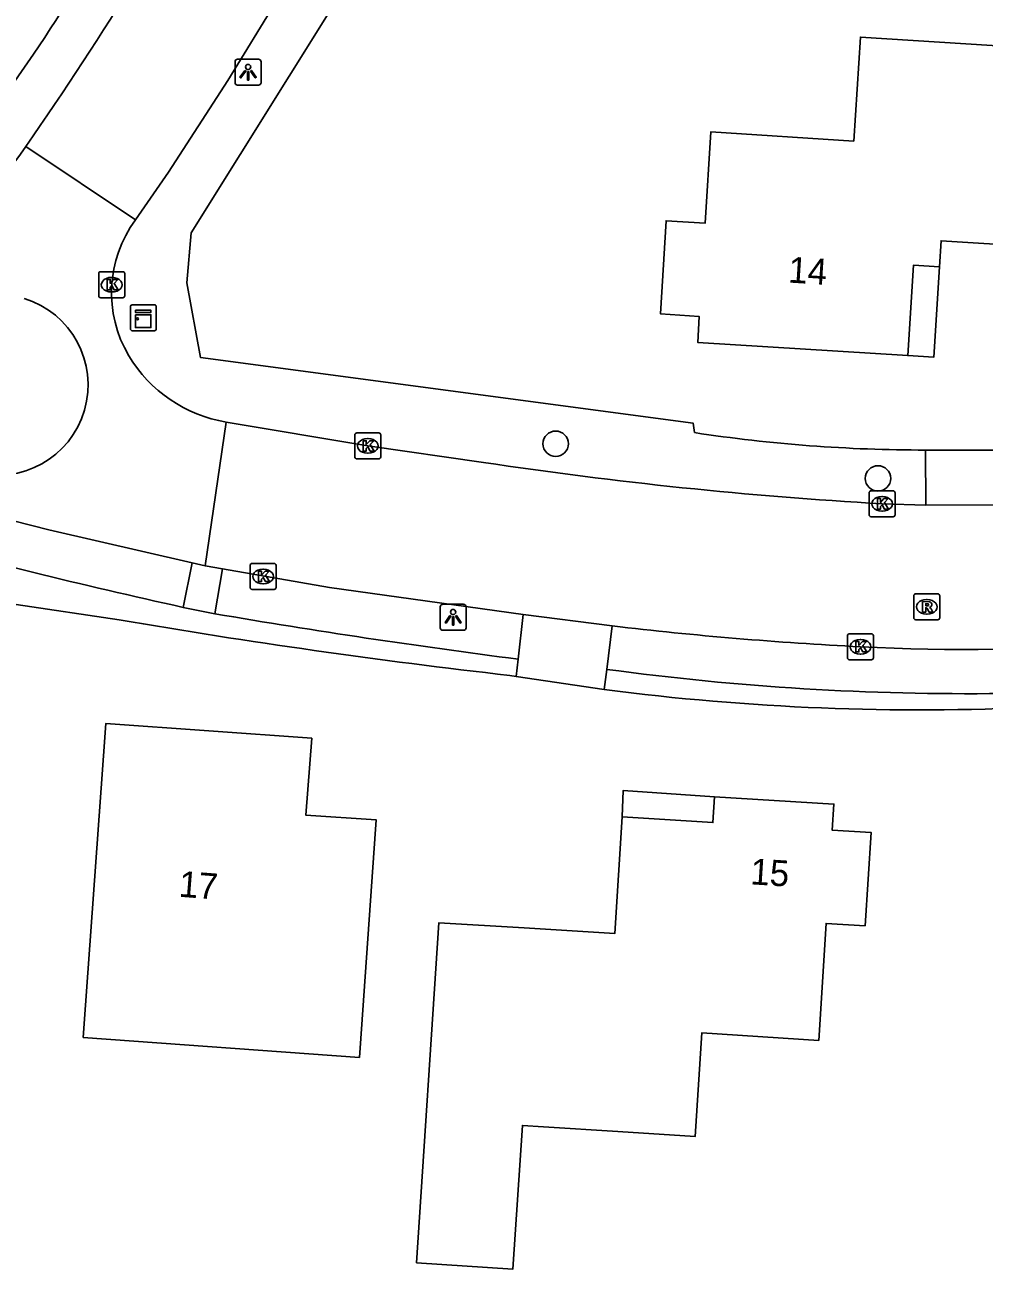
# Model space of a CAD drawing. Extents: x 162675 to 163482, y 379761 to 381227.
# Drawn here: x 163128.52 to 163165.45, y 380867.2 to 380915.09 of the extents above; entities that cross this region are included whole.
import ezdxf

# ---------------------------------------------------------------- set-up
doc = ezdxf.new("R2010")
doc.units = 0
for name, color, linetype in [('IMGEO_Berm_groen', 7, 'Continuous'), ('IMGEO_Boom', 7, 'Continuous'), ('IMGEO_Groenvoorziening', 7, 'Continuous'), ('IMGEO_Haag', 7, 'Continuous'), ('IMGEO_Hek', 7, 'Continuous'), ('IMGEO_Kast', 7, 'Continuous'), ('IMGEO_Kolk', 7, 'Continuous'), ('IMGEO_Lichtpunt', 7, 'Continuous'), ('IMGEO_Pand', 7, 'Continuous'), ('IMGEO_Pand_nummerreeks', 7, 'Continuous'), ('IMGEO_Pand_overbouw', 7, 'Continuous'), ('IMGEO_Parkeervlak_halfverhard', 7, 'Continuous'), ('IMGEO_Rijbaan_lokaal_gesloten', 7, 'Continuous'), ('IMGEO_Rijbaan_lokaal_open', 7, 'Continuous'), ('IMGEO_Rioolput', 7, 'Continuous'), ('IMGEO_Voetpad_open', 7, 'Continuous')]:
    doc.layers.add(name, color=color, linetype=linetype)

msp = doc.modelspace()

# ---------------------------------------------------------------- linework, layer by layer
at = {"layer": 'IMGEO_Berm_groen'}
msp.add_lwpolyline([(163150.959, 380936.325), (163144.291, 380922.073), (163134.917, 380907.085), (163134.757, 380905.164), (163135.284, 380902.281), (163154.247, 380899.765), (163154.294, 380899.394)], dxfattribs=at)
msp.add_arc((163163.182, 380958.103), 59.378, 261.39114, 270.01327, dxfattribs=at)
at = {"layer": 'IMGEO_Boom'}
for centre in [(163148.955, 380898.967), (163161.365, 380897.632)]:
    msp.add_circle(centre, 0.489, dxfattribs=at)
at = {"layer": 'IMGEO_Groenvoorziening'}
for points in [[(163128.179, 380892.783), (163132.144, 380892.19)], [(163147.191, 380890.047), (163147.437, 380890.008)]]:
    msp.add_lwpolyline(points, dxfattribs=at)
msp.add_arc((163177.842, 381159.158), 270.851, 260.28663, 263.50221, dxfattribs=at)
at = {"layer": 'IMGEO_Haag'}
msp.add_arc((163162.97, 380982.847), 94.126, 262.58307, 283.03541, dxfattribs=at)
at = {"layer": 'IMGEO_Hek'}
for points in [[(163134.917, 380907.085), (163144.291, 380922.073), (163150.959, 380936.325)], [(163154.247, 380899.765), (163135.284, 380902.281), (163134.757, 380905.164), (163134.917, 380907.085)]]:
    msp.add_lwpolyline(points, dxfattribs=at)
at = {"layer": 'IMGEO_Kast'}
for p, q in [((163132.654, 380904.315), (163133.495, 380904.315)), ((163133.495, 380904.315), (163132.654, 380904.315)), ((163132.579, 380903.39), (163132.579, 380904.231)), ((163132.579, 380904.231), (163132.579, 380903.39)), ((163133.579, 380904.24), (163133.579, 380903.399)), ((163133.579, 380903.399), (163133.579, 380904.24)), ((163133.504, 380903.315), (163132.663, 380903.315)), ((163132.663, 380903.315), (163133.504, 380903.315))]:
    msp.add_line(p, q, dxfattribs=at)
for points in [[(163132.774, 380904.105), (163133.374, 380904.105), (163133.374, 380904.02), (163132.774, 380904.02), (163132.774, 380904.105)], [(163132.774, 380903.93), (163133.374, 380903.93), (163133.374, 380903.441), (163132.774, 380903.441), (163132.774, 380903.93)]]:
    msp.add_lwpolyline(points, dxfattribs=at)
msp.add_circle((163132.858, 380903.779), 0.0377, dxfattribs=at)
for centre, start, end in [((163132.657, 380904.237), 92.4484, 184.2845), ((163132.657, 380904.237), 92.4484, 184.2845), ((163133.501, 380904.237), 2.4484, 94.2845), ((163133.501, 380904.237), 2.4484, 94.2845), ((163132.657, 380903.393), 182.4484, 274.2845), ((163132.657, 380903.393), 182.4484, 274.2845), ((163133.501, 380903.393), 272.4484, 4.2845), ((163133.501, 380903.393), 272.4484, 4.2845)]:
    msp.add_arc(centre, 0.0779, start, end, dxfattribs=at)
at = {"layer": 'IMGEO_Kolk'}
for p, q in [((163131.362, 380904.664), (163131.362, 380905.516)), ((163131.437, 380905.59), (163132.289, 380905.59)), ((163131.85, 380905.37), (163131.875, 380905.37)), ((163132.363, 380905.516), (163132.363, 380904.664)), ((163131.873, 380904.81), (163131.848, 380904.81)), ((163132.289, 380904.59), (163131.437, 380904.59)), ((163141.221, 380898.458), (163141.221, 380899.31)), ((163141.296, 380899.384), (163142.148, 380899.384)), ((163141.709, 380899.164), (163141.734, 380899.164)), ((163142.222, 380899.31), (163142.222, 380898.458)), ((163141.732, 380898.604), (163141.707, 380898.604)), ((163142.148, 380898.384), (163141.296, 380898.384)), ((163161.097, 380897.155), (163161.949, 380897.155)), ((163161.022, 380896.229), (163161.022, 380897.081)), ((163161.51, 380896.935), (163161.535, 380896.935)), ((163162.023, 380897.081), (163162.023, 380896.229)), ((163161.533, 380896.375), (163161.508, 380896.375)), ((163161.949, 380896.155), (163161.097, 380896.155)), ((163137.191, 380893.433), (163137.191, 380894.285)), ((163137.266, 380894.359), (163138.118, 380894.359)), ((163138.192, 380894.285), (163138.192, 380893.433)), ((163137.679, 380894.139), (163137.704, 380894.139)), ((163138.118, 380893.359), (163137.266, 380893.359)), ((163137.702, 380893.579), (163137.677, 380893.579)), ((163160.189, 380890.726), (163160.189, 380891.578)), ((163160.264, 380891.652), (163161.116, 380891.652)), ((163160.677, 380891.432), (163160.702, 380891.432)), ((163161.19, 380891.578), (163161.19, 380890.726)), ((163161.116, 380890.652), (163160.264, 380890.652)), ((163160.7, 380890.872), (163160.675, 380890.872))]:
    msp.add_line(p, q, dxfattribs=at)
for points in [[(163131.362, 380904.664), (163131.362, 380905.516)], [(163131.437, 380905.59), (163132.289, 380905.59)], [(163131.683, 380905.29), (163131.806, 380905.29), (163131.806, 380905.139), (163131.936, 380905.29), (163132.1, 380905.29), (163131.954, 380905.139), (163132.107, 380904.89), (163131.955, 380904.89), (163131.87, 380905.054), (163131.806, 380904.987), (163131.806, 380904.89), (163131.683, 380904.89), (163131.683, 380905.29)], [(163132.363, 380905.516), (163132.363, 380904.664)], [(163132.289, 380904.59), (163131.437, 380904.59)], [(163141.221, 380898.458), (163141.221, 380899.31)], [(163141.296, 380899.384), (163142.148, 380899.384)], [(163141.542, 380899.084), (163141.665, 380899.084), (163141.665, 380898.933), (163141.795, 380899.084), (163141.959, 380899.084), (163141.813, 380898.933), (163141.966, 380898.684), (163141.814, 380898.684), (163141.729, 380898.848), (163141.665, 380898.781), (163141.665, 380898.684), (163141.542, 380898.684), (163141.542, 380899.084)], [(163142.222, 380899.31), (163142.222, 380898.458)], [(163142.148, 380898.384), (163141.296, 380898.384)], [(163161.097, 380897.155), (163161.949, 380897.155)], [(163161.022, 380896.229), (163161.022, 380897.081)], [(163161.343, 380896.855), (163161.466, 380896.855), (163161.466, 380896.704), (163161.596, 380896.855), (163161.76, 380896.855), (163161.614, 380896.704), (163161.767, 380896.455), (163161.615, 380896.455), (163161.53, 380896.619), (163161.466, 380896.552), (163161.466, 380896.455), (163161.343, 380896.455), (163161.343, 380896.855)], [(163162.023, 380897.081), (163162.023, 380896.229)], [(163161.949, 380896.155), (163161.097, 380896.155)], [(163137.191, 380893.433), (163137.191, 380894.285)], [(163137.266, 380894.359), (163138.118, 380894.359)], [(163138.192, 380894.285), (163138.192, 380893.433)], [(163137.512, 380894.059), (163137.635, 380894.059), (163137.635, 380893.908), (163137.765, 380894.059), (163137.929, 380894.059), (163137.783, 380893.908), (163137.936, 380893.659), (163137.784, 380893.659), (163137.699, 380893.823), (163137.635, 380893.756), (163137.635, 380893.659), (163137.512, 380893.659), (163137.512, 380894.059)], [(163138.118, 380893.359), (163137.266, 380893.359)], [(163160.189, 380890.726), (163160.189, 380891.578)], [(163160.264, 380891.652), (163161.116, 380891.652)], [(163161.19, 380891.578), (163161.19, 380890.726)], [(163160.51, 380891.352), (163160.633, 380891.352), (163160.633, 380891.201), (163160.763, 380891.352), (163160.927, 380891.352), (163160.781, 380891.201), (163160.934, 380890.952), (163160.782, 380890.952), (163160.697, 380891.116), (163160.633, 380891.049), (163160.633, 380890.952), (163160.51, 380890.952), (163160.51, 380891.352)], [(163161.116, 380890.652), (163160.264, 380890.652)]]:
    msp.add_lwpolyline(points, dxfattribs=at)
for centre, start, end in [((163131.439, 380905.514), 91.552, 178.448), ((163131.439, 380905.514), 91.552, 178.448), ((163132.287, 380905.514), 1.552, 88.448), ((163132.287, 380905.514), 1.552, 88.448), ((163131.439, 380904.666), 181.552, 268.448), ((163131.439, 380904.666), 181.552, 268.448), ((163132.287, 380904.666), 271.552, 358.448), ((163132.287, 380904.666), 271.552, 358.448), ((163141.298, 380899.308), 91.552, 178.448), ((163141.298, 380899.308), 91.552, 178.448), ((163142.146, 380899.308), 1.552, 88.448), ((163142.146, 380899.308), 1.552, 88.448), ((163141.298, 380898.46), 181.552, 268.448), ((163141.298, 380898.46), 181.552, 268.448), ((163142.146, 380898.46), 271.552, 358.448), ((163142.146, 380898.46), 271.552, 358.448), ((163161.099, 380897.079), 91.552, 178.448), ((163161.099, 380897.079), 91.552, 178.448), ((163161.947, 380897.079), 1.552, 88.448), ((163161.947, 380897.079), 1.552, 88.448), ((163161.099, 380896.231), 181.552, 268.448), ((163161.099, 380896.231), 181.552, 268.448), ((163161.947, 380896.231), 271.552, 358.448), ((163161.947, 380896.231), 271.552, 358.448), ((163137.268, 380894.283), 91.552, 178.448), ((163137.268, 380894.283), 91.552, 178.448), ((163138.116, 380894.283), 1.552, 88.448), ((163138.116, 380894.283), 1.552, 88.448), ((163137.268, 380893.435), 181.552, 268.448), ((163137.268, 380893.435), 181.552, 268.448), ((163138.116, 380893.435), 271.552, 358.448), ((163138.116, 380893.435), 271.552, 358.448), ((163160.266, 380891.576), 91.552, 178.448), ((163160.266, 380891.576), 91.552, 178.448), ((163161.114, 380891.576), 1.552, 88.448), ((163161.114, 380891.576), 1.552, 88.448), ((163160.266, 380890.728), 181.552, 268.448), ((163160.266, 380890.728), 181.552, 268.448), ((163161.114, 380890.728), 271.552, 358.448), ((163161.114, 380890.728), 271.552, 358.448)]:
    msp.add_arc(centre, 0.0765, start, end, dxfattribs=at)
for centre, major_axis, ratio, start_param, end_param in [((163131.849, 380905.09), (-0.387, 0.002), 0.722429, 4.712389, 7.853982), ((163131.874, 380905.09), (-0.39, 0.002), 0.717154, 1.570796, 4.712389), ((163141.708, 380898.884), (-0.387, 0.002), 0.722429, 4.712389, 7.853982), ((163141.733, 380898.884), (-0.39, 0.002), 0.717154, 1.570796, 4.712389), ((163161.509, 380896.655), (-0.387, 0.002), 0.722429, 4.712389, 7.853982), ((163161.534, 380896.655), (-0.39, 0.002), 0.717154, 1.570796, 4.712389), ((163137.678, 380893.859), (-0.387, 0.002), 0.722429, 4.712389, 7.853982), ((163137.703, 380893.859), (-0.39, 0.002), 0.717154, 1.570796, 4.712389), ((163160.676, 380891.152), (-0.387, 0.002), 0.722429, 4.712389, 7.853982), ((163160.701, 380891.152), (-0.39, 0.002), 0.717154, 1.570796, 4.712389)]:
    msp.add_ellipse(centre, major_axis=major_axis, ratio=ratio, start_param=start_param, end_param=end_param, dxfattribs=at)
at = {"layer": 'IMGEO_Lichtpunt'}
for p, q in [((163136.614, 380913.673), (163136.614, 380912.866)), ((163136.614, 380913.673), (163136.614, 380912.866)), ((163137.516, 380913.768), (163136.708, 380913.768)), ((163137.516, 380913.768), (163136.708, 380913.768)), ((163137.61, 380912.866), (163137.61, 380913.673)), ((163137.61, 380912.866), (163137.61, 380913.673)), ((163136.708, 380912.772), (163137.516, 380912.772)), ((163136.708, 380912.772), (163137.516, 380912.772)), ((163144.509, 380892.691), (163144.509, 380891.884)), ((163144.509, 380892.691), (163144.509, 380891.884)), ((163145.411, 380892.786), (163144.603, 380892.786)), ((163145.411, 380892.786), (163144.603, 380892.786)), ((163145.505, 380891.884), (163145.505, 380892.691)), ((163145.505, 380891.884), (163145.505, 380892.691)), ((163144.603, 380891.79), (163145.411, 380891.79)), ((163144.603, 380891.79), (163145.411, 380891.79))]:
    msp.add_line(p, q, dxfattribs=at)
for points in [[(163136.988, 380913.337), (163137.027, 380913.309), (163136.839, 380913.047), (163136.801, 380913.074), (163136.988, 380913.337)], [(163137.09, 380913.289), (163137.137, 380913.289), (163137.137, 380912.967), (163137.09, 380912.967), (163137.09, 380913.289)], [(163137.2, 380913.309), (163137.238, 380913.336), (163137.425, 380913.074), (163137.386, 380913.046), (163137.2, 380913.309)], [(163144.883, 380892.355), (163144.922, 380892.327), (163144.734, 380892.065), (163144.696, 380892.092), (163144.883, 380892.355)], [(163145.095, 380892.327), (163145.133, 380892.354), (163145.32, 380892.092), (163145.281, 380892.064), (163145.095, 380892.327)], [(163144.985, 380892.307), (163145.032, 380892.307), (163145.032, 380891.985), (163144.985, 380891.985), (163144.985, 380892.307)]]:
    msp.add_lwpolyline(points, dxfattribs=at)
for centre in [(163137.113, 380913.471), (163145.008, 380892.489)]:
    msp.add_circle(centre, 0.0994, dxfattribs=at)
for centre, start, end in [((163136.708, 380913.673), 90, 180), ((163136.708, 380913.673), 90, 180), ((163137.516, 380913.673), 0, 90), ((163137.516, 380913.673), 0, 90), ((163136.708, 380912.866), 180, 270), ((163136.708, 380912.866), 180, 270), ((163137.516, 380912.866), 270, 0), ((163137.516, 380912.866), 270, 360), ((163144.603, 380892.691), 90, 180), ((163144.603, 380892.691), 90, 180), ((163145.411, 380892.691), 0, 90), ((163145.411, 380892.691), 0, 90), ((163144.603, 380891.884), 180, 270), ((163144.603, 380891.884), 180, 270), ((163145.411, 380891.884), 270, 0), ((163145.411, 380891.884), 270, 360)]:
    msp.add_arc(centre, 0.0946, start, end, dxfattribs=at)
at = {"layer": 'IMGEO_Pand'}
for points in [[(163167.301, 380906.556), (163163.797, 380906.782), (163163.734, 380905.78), (163162.733, 380905.845), (163162.509, 380902.361), (163154.423, 380902.867), (163154.485, 380903.865), (163152.995, 380903.967), (163153.206, 380907.548), (163154.713, 380907.459), (163154.924, 380910.971), (163160.432, 380910.617), (163160.69, 380914.623), (163167.791, 380914.166), (163167.301, 380906.556)], [(163139.561, 380887.631), (163139.335, 380884.676), (163142.044, 380884.484), (163141.397, 380875.344), (163130.765, 380876.113), (163131.636, 380888.202), (163139.561, 380887.631)], [(163160.874, 380880.405), (163159.367, 380880.501), (163159.082, 380876.002), (163154.582, 380876.286), (163154.329, 380872.306), (163151.349, 380872.495), (163148.481, 380872.677), (163147.673, 380872.728), (163147.308, 380867.196), (163143.6, 380867.44), (163144.462, 380880.529), (163147.738, 380880.334), (163151.228, 380880.113), (163151.513, 380884.601), (163155.007, 380884.383), (163155.069, 380885.381), (163159.668, 380885.094), (163159.606, 380884.092), (163161.103, 380883.997), (163160.874, 380880.405)]]:
    msp.add_lwpolyline(points, dxfattribs=at)
at = {"layer": 'IMGEO_Pand_overbouw'}
for points in [[(163163.734, 380905.78), (163162.733, 380905.845), (163162.509, 380902.361), (163163.51, 380902.296)], [(163151.513, 380884.601), (163155.007, 380884.383), (163155.069, 380885.381), (163151.556, 380885.621)]]:
    msp.add_lwpolyline(points, close=True, dxfattribs=at)
at = {"layer": 'IMGEO_Parkeervlak_halfverhard'}
for centre, radius, start, end in [((163194.221, 381161.87), 275.72, 255.03912, 257.51575), ((163185.277, 381182.955), 294.711, 260.34203, 262.63724), ((163164.796, 380992.595), 103.249, 262.27659, 270.74101)]:
    msp.add_arc(centre, radius, start, end, dxfattribs=at)
at = {"layer": 'IMGEO_Rijbaan_lokaal_gesloten'}
for points in [[(163135.459, 380894.27), (163136.273, 380899.799)], [(163146.174, 380898.249), (163141.722, 380898.884), (163136.273, 380899.799)], [(163163.211, 380896.599), (163161.523, 380896.655)], [(163166.688, 380896.61), (163163.211, 380896.599)], [(163135.459, 380894.27), (163136.125, 380894.154)], [(163136.125, 380894.154), (163140.243, 380893.436), (163147.698, 380892.391)], [(163147.698, 380892.391), (163151.135, 380891.952)]]:
    msp.add_lwpolyline(points, dxfattribs=at)
for centre, radius, start, end in [((163171.214, 381064.666), 168.29, 261.44324, 266.69888), ((163164.628, 380965.655), 74.607, 266.97411, 282.88631), ((163167.855, 381034.195), 143.222, 263.29575, 267.13231)]:
    msp.add_arc(centre, radius, start, end, dxfattribs=at)
at = {"layer": 'IMGEO_Rijbaan_lokaal_open'}
for points in [[(163132.774, 380907.581), (163134.045, 380909.421), (163136.337, 380912.952), (163138.222, 380916.035), (163141.275, 380921.455), (163145.775, 380930.65), (163149.406, 380938.711)], [(163132.774, 380907.581), (163128.552, 380910.413)], [(163103.586, 380902.166), (163107.294, 380901.282), (163123.332, 380897.204), (163129.44, 380895.655), (163134.958, 380894.385)], [(163134.958, 380894.385), (163135.459, 380894.27)]]:
    msp.add_lwpolyline(points, dxfattribs=at)
for centre, radius, start, end in [((163013.842, 380990.197), 139.728, 325.18028, 331.61858), ((163014.881, 380989.462), 138.455, 322.79452, 325.18429), ((163136.589, 380904.774), 4.736, 143.6484, 210.7219), ((163127.474, 380901.232), 3.477, 254.4911, 73.0953), ((163137.192, 380905.189), 5.467, 211.228, 260.3214)]:
    msp.add_arc(centre, radius, start, end, dxfattribs=at)
at = {"layer": 'IMGEO_Rioolput'}
for p, q in [((163162.743, 380892.264), (163162.743, 380893.116)), ((163162.818, 380893.19), (163163.67, 380893.19)), ((163163.231, 380892.97), (163163.256, 380892.97)), ((163163.744, 380893.116), (163163.744, 380892.264)), ((163163.254, 380892.41), (163163.229, 380892.41)), ((163163.67, 380892.19), (163162.818, 380892.19))]:
    msp.add_line(p, q, dxfattribs=at)
for points in [[(163162.743, 380892.264), (163162.743, 380893.116)], [(163162.818, 380893.19), (163163.67, 380893.19)], [(163163.332, 380892.888), (163163.08, 380892.89), (163163.08, 380892.49)], [(163163.744, 380893.116), (163163.744, 380892.264)], [(163163.08, 380892.49), (163163.204, 380892.49), (163163.204, 380892.652), (163163.215, 380892.652)], [(163163.258, 380892.809), (163163.204, 380892.809), (163163.204, 380892.728)], [(163163.204, 380892.728), (163163.256, 380892.728)], [(163163.262, 380892.623), (163163.333, 380892.49), (163163.473, 380892.49), (163163.408, 380892.616)], [(163163.67, 380892.19), (163162.818, 380892.19)]]:
    msp.add_lwpolyline(points, dxfattribs=at)
for centre, radius, start, end in [((163162.82, 380893.114), 0.0765, 91.552, 178.448), ((163162.82, 380893.114), 0.0765, 91.552, 178.448), ((163163.331, 380892.778), 0.109, 350.3612, 89.416), ((163163.668, 380893.114), 0.0765, 1.552, 88.448), ((163163.668, 380893.114), 0.0765, 1.552, 88.448), ((163163.214, 380892.599), 0.0533, 26.0293, 88.6989), ((163163.24, 380892.917), 0.19, 274.7715, 282.9687), ((163163.264, 380892.713), 0.0964, 77.0061, 93.1865), ((163163.278, 380892.77), 0.0378, 276.6634, 79.6772), ((163163.329, 380892.778), 0.112, 277.5842, 350.9817), ((163163.313, 380892.563), 0.108, 29.5134, 73.7905), ((163162.82, 380892.266), 0.0765, 181.552, 268.448), ((163162.82, 380892.266), 0.0765, 181.552, 268.448), ((163163.668, 380892.266), 0.0765, 271.552, 358.448), ((163163.668, 380892.266), 0.0765, 271.552, 358.448)]:
    msp.add_arc(centre, radius, start, end, dxfattribs=at)
for centre, major_axis, ratio, start_param, end_param in [((163163.23, 380892.69), (-0.387, 0.002), 0.722429, 4.712389, 7.853982), ((163163.255, 380892.69), (-0.39, 0.002), 0.717154, 1.570796, 4.712389)]:
    msp.add_ellipse(centre, major_axis=major_axis, ratio=ratio, start_param=start_param, end_param=end_param, dxfattribs=at)
at = {"layer": 'IMGEO_Voetpad_open'}
for points in [[(163125.413, 380909.007), (163128.856, 380913.957)], [(163163.196, 380898.725), (163166.684, 380898.722), (163166.702, 380898.723), (163166.72, 380898.725)], [(163163.211, 380896.599), (163163.196, 380898.725)], [(163134.958, 380894.385), (163134.618, 380892.669)], [(163135.835, 380892.421), (163136.125, 380894.154)], [(163135.835, 380892.421), (163134.618, 380892.669)], [(163147.698, 380892.391), (163147.51, 380890.674)], [(163150.92, 380890.283), (163151.135, 380891.952)], [(163147.437, 380890.008), (163147.51, 380890.674)], [(163150.819, 380889.509), (163147.437, 380890.008)], [(163150.92, 380890.283), (163150.819, 380889.509)]]:
    msp.add_lwpolyline(points, dxfattribs=at)
msp.add_arc((163006.679, 380994.994), 146.609, 326.44487, 331.31361, dxfattribs=at)

# ---------------------------------------------------------------- texts
at = {"layer": 'IMGEO_Pand_nummerreeks'}
for s, rotation, p in [('14', 356.4247, (163157.89, 380905.174)), ('15', 356.4305, (163156.43, 380882.01)), ('17', 355.571, (163134.422, 380881.533))]:
    msp.add_text(s, height=1, rotation=rotation, dxfattribs=at).set_placement(p)

doc.saveas('drawing.dxf')
